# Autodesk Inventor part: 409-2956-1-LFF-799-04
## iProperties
Created: 2010-11
Part Number: 409-2956-1-LFF-799-04
Material: 3/4" OD TUBE - SS
Document SubType Name: Modeling
Designer: S. Boerckel
Engineer: Steve Boerckel
Mass: 731.966 g
Surface Area: 1099.2 cm^2
Volume: 90.5898 cm^3
Density: 8.08 g/cm^3
Description: DRAIN TUBING
Length: 39.521 in
Author: S. Boerckel
Revision Number: 0
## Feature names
1. Sweep2
